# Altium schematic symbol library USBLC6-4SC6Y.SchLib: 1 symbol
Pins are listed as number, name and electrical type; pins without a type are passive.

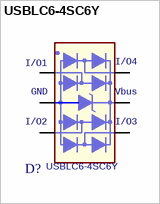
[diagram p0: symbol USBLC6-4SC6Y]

## USBLC6-4SC6Y
designator D?
footprint ST_SOT23-6L
pins: 1 I/O1, 2 GND, 3 I/O2, 4 I/O3, 5 Vbus, 6 I/O4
